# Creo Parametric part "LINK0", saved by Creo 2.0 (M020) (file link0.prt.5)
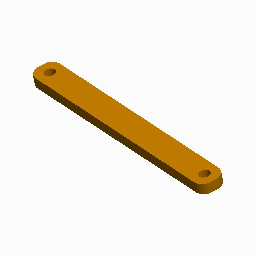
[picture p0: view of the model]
Units: Inch lbm Second (Pro/E Default); INCH, POUND, SECS

Created from: INLBS_PART_SOLID.PRT

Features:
  1. datum plane "RIGHT"
  2. datum plane "TOP"
  3. datum plane "FRONT"
  4. coordinate system
  5. sketch "Sketch 1"
  6. extrusion "Extrude 1", "Sketch 1"
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
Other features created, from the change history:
  datum plane "DTM1"
  datum plane "BOTTON"
  round "Round 1"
